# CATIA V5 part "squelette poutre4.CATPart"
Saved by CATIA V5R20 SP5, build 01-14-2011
Part number: squelette poutre4
Bounding box of the stored display mesh (mm): x 0 to 300, y 280 to 1500.199, z 309.845 to 890.138
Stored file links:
  F:\iao fini\squelette poutre4.CATPart
  F:\iao fini\iao-finipbgliss.CATProduct
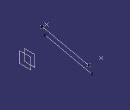
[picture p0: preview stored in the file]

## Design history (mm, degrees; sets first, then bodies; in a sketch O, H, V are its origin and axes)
External parameters (linked from other documents)
  External.L_poutre3 = 1120 mm
Set1
  Plane1 "Planbielle": linked copy from another document
  Point1: linked copy from another document
  Point2: linked copy from another document
  Line1: linked copy from another document
Set2
  Point3: type OnPlane, Support Plane2, RefPoint Point1, H 0, V 0, Direction (0, 1, 0)
  Point4: type OnPlane, Support Plane2, RefPoint Point2, H 0, V 0, Direction (0, 1, 0)
  Line2: type PtDir, RefPoint Point3, Direction Line1, Support Plane2, Start 0, End 1120 {= External.L_poutre3}
Body1 (main body)
  Set3
    Plane2 "Plan4": type Offset, RefPlane yz-plane, Offset 300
